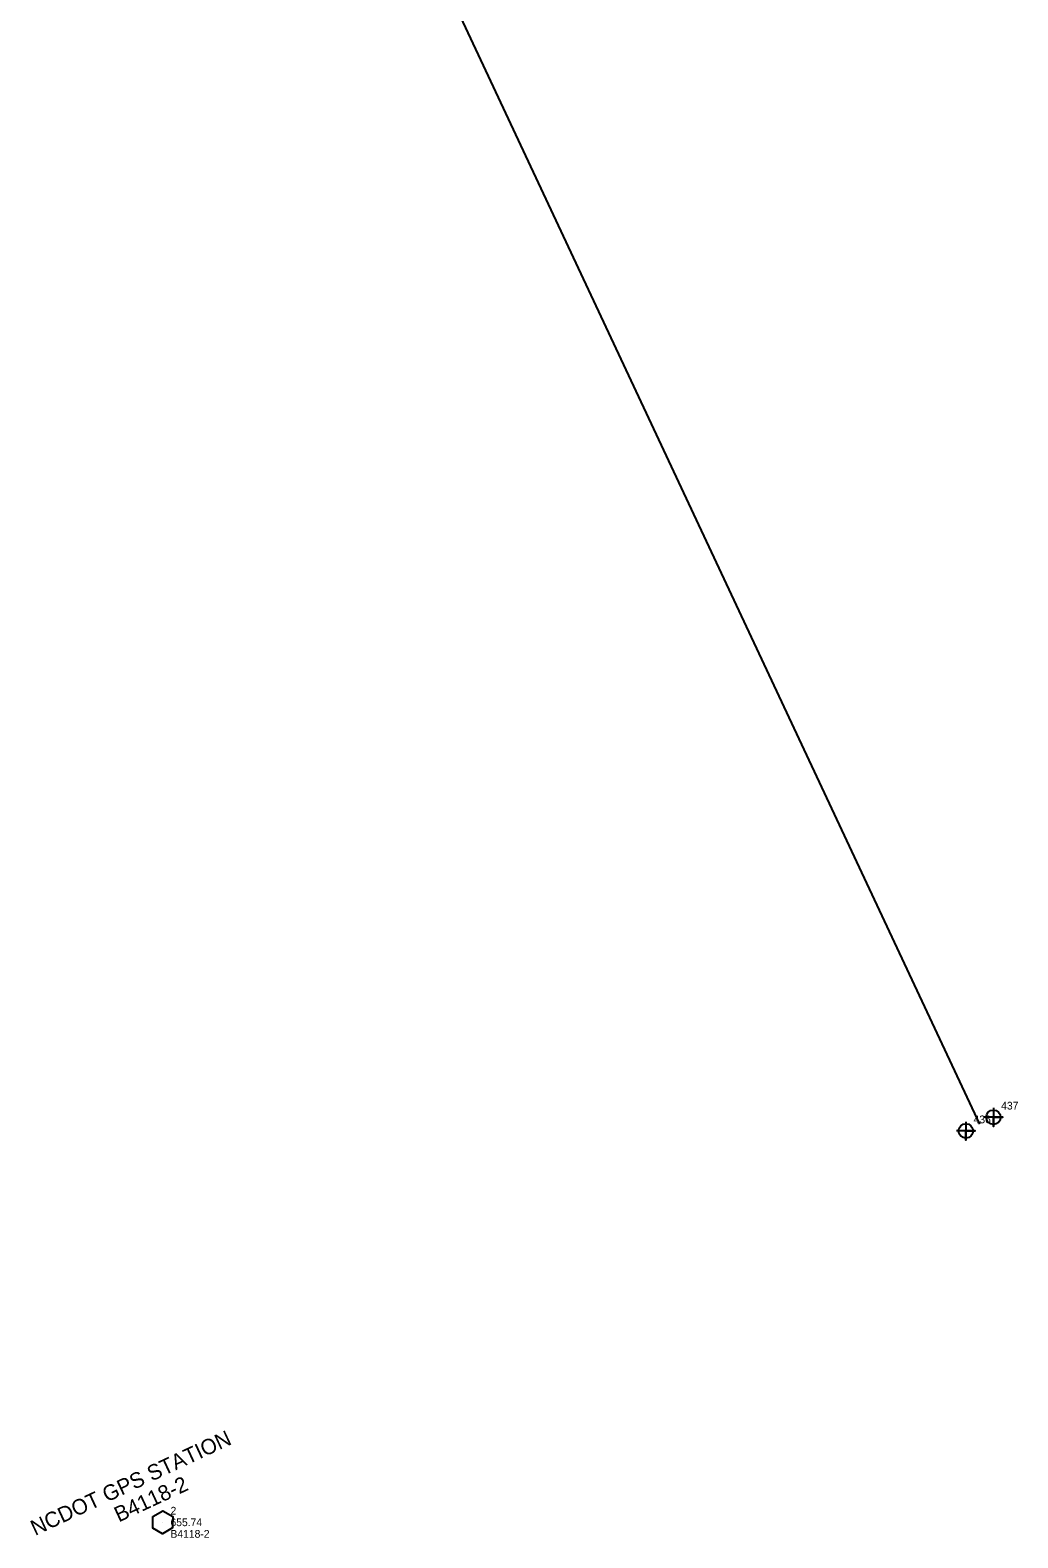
# Model space of a CAD drawing. Extents: x 1380524 to 1382335, y 594765 to 596944.
# Drawn here: x 1381765.6 to 1382085.3, y 594765.5 to 595253.4 of the extents above; entities that cross this region are included whole.
import ezdxf

# ---------------------------------------------------------------- set-up
doc = ezdxf.new("R2010")
doc.units = 0
for name, color, linetype in [('CTL GPS Vertical CELL', 7, 'Continuous'), ('CTL GPS Vertical Cogo Comment', 7, 'Continuous'), ('CTL GPS Vertical Cogo Elevation', 7, 'Continuous'), ('CTL GPS Vertical Cogo Number', 7, 'Continuous'), ('CTL GPS Vertical Text', 7, 'Continuous'), ('Exist Utilities Gas UG Line', 7, 'Continuous'), ('Exist Utilities Gas UG Line Cogo Number', 7, 'Continuous'), ('Exist Utilities Gas UG Line Cogo Point CELL', 7, 'Continuous')]:
    doc.layers.add(name, color=color, linetype=linetype)

msp = doc.modelspace()

# ---------------------------------------------------------------- linework, layer by layer
at = {"layer": 'CTL GPS Vertical CELL'}
msp.add_line((1381808.53, 594770.52), (1381808.53, 594770.52), dxfattribs=at)
msp.add_lwpolyline([(1381805.3, 594772.39), (1381808.55, 594774.2), (1381811.8, 594772.41), (1381811.75, 594768.69), (1381808.5, 594766.8), (1381805.3, 594768.61)], close=True, dxfattribs=at)
at = {"layer": 'Exist Utilities Gas UG Line'}
msp.add_lwpolyline([(1381819.69, 595439.52), (1382072.96, 594899.37)], dxfattribs=at)
at = {"layer": 'Exist Utilities Gas UG Line Cogo Point CELL'}
for points in [[(1382077.42, 594904.59), (1382077.42, 594898.59), (1382077.42, 594901.59), (1382080.42, 594901.59), (1382074.42, 594901.59)], [(1382068.5, 594900.15), (1382068.5, 594894.15), (1382068.5, 594897.15), (1382071.5, 594897.15), (1382065.5, 594897.15)]]:
    msp.add_lwpolyline(points, dxfattribs=at)
for centre in [(1382077.42, 594901.59), (1382068.5, 594897.15)]:
    msp.add_circle(centre, 2.34, dxfattribs=at)

# ---------------------------------------------------------------- texts
at = {"layer": 'CTL GPS Vertical Cogo Comment'}
msp.add_text('B4118-2', height=2.5, dxfattribs=at).set_placement((1381811.06, 594765.51))
at = {"layer": 'CTL GPS Vertical Cogo Elevation'}
msp.add_text('655.74', height=2.5, dxfattribs=at).set_placement((1381811.06, 594769.26))
at = {"layer": 'CTL GPS Vertical Cogo Number'}
msp.add_text('2', height=2.5, dxfattribs=at).set_placement((1381811.06, 594773.01))
at = {"layer": 'CTL GPS Vertical Text'}
for s, p in [('NCDOT GPS STATION', (1381767.25, 594766.08)), ('B4118-2', (1381794.32, 594770.43))]:
    msp.add_text(s, height=5, rotation=25, dxfattribs=at).set_placement(p)
at = {"layer": 'Exist Utilities Gas UG Line Cogo Number'}
for s, p in [('437', (1382079.92, 594904.09)), ('436', (1382071, 594899.65))]:
    msp.add_text(s, height=2.5, dxfattribs=at).set_placement(p)

doc.saveas('drawing.dxf')
